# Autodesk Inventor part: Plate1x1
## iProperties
Created: 2006-02
Part Number: Plate1x1
Material: Stainless Steel
Document SubType Name: Modeling
Designer: 40664
Mass: 252096 g
Surface Area: 63160 cm^2
Volume: 31200 cm^3
Density: 8.08 g/cm^3
CSToolsMass: 252.0
CSToolsVolume: 31200000.0
CSToolsArea: 63160.0
Author: 40664
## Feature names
1. Extrusion1
